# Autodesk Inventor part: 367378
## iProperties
Created: 2006-09
Part Number: 367378
Material: 8.8 vz
Description: Zylinderschraube
Vendor: Autodesk Inc.
Document SubType Name: Modeling
Standard: DIN 912
Designer: I.Baliuc
Standards Organization: DIN
Language: de-DE
Size Designation: M8 x 30
Categories: <MemberInstance Version="R10.0.0"><Categories><Category DisplayName="Schrauben" InternalName="e4da775c-781d-43d5-af7c-5136215cf5a6" Mnemonic="FSTN"><Category Di
Density: 7.85 g/cm^3
Mass: 18.9051 g
Surface Area: 14.1143 cm^2
Volume: 2.4083 cm^3
Abmessung: M8 x 30
Author: T.Messerschmitt
Comments: DIN 912 - M8 x 30
Revision Number: 367378
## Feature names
1. Körper [Revolution]
2. Loch [Extrusion]
3. Rundung1 [Fillet]
4. Fase1 [Chamfer]
